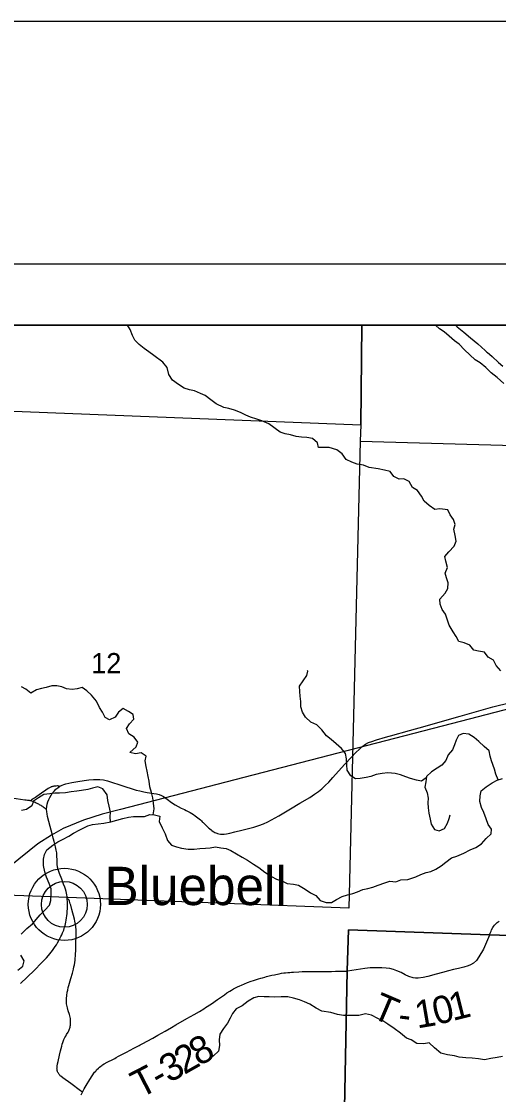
# Model space of a CAD drawing. Extents: x 0 to 34, y 0 to 22.
# Drawn here: x 4.145 to 5.129, y 19.787 to 22 of the extents above; entities that cross this region are included whole.
import ezdxf

# ---------------------------------------------------------------- set-up
doc = ezdxf.new("R2010")
doc.units = 0
for name, color, linetype in [('GM_X_Corporation', 7, 'Continuous'), ('GM_X_County_Road', 7, 'Continuous'), ('GM_X_Minor_River', 7, 'Continuous'), ('GM_X_Rail_Line', 7, 'Continuous'), ('GM_X_Section_Text', 7, 'Continuous'), ('GM_X_State_Route', 7, 'Continuous'), ('GM_X_Township_Road', 7, 'Continuous'), ('GM_X_Township_Road_Text', 7, 'Continuous'), ('GM_X_Unincorporated', 7, 'Continuous'), ('GM_X_Unincorporated_Location', 7, 'Continuous'), ('GM_X_Unincorporated_Text', 7, 'Continuous'), ('SH_Border', 7, 'Continuous'), ('SH_Cut_Line', 7, 'Continuous'), ('SH_Text', 7, 'Continuous')]:
    doc.layers.add(name, color=color, linetype=linetype)

msp = doc.modelspace()

# ---------------------------------------------------------------- linework, layer by layer
at = {"layer": 'GM_X_Corporation'}
for points in [[(4.7823, 18.128), (4.7905, 18.3604), (4.8074, 19.5455), (4.8169, 20.042), (4.8194, 20.1261), (5.11, 20.116), (6.0551, 20.0845), (6.4901, 20.0752), (6.7204, 20.0659), (7.3691, 20.0515), (7.3901, 20.051), (7.814, 20.0425), (8.4311, 20.028), (8.4311, 21.3734), (1.6311, 21.3734)], [(4.0508, 18.1454), (4.7823, 18.128), (4.7905, 18.3604), (4.8074, 19.5455), (4.8169, 20.042), (4.8194, 20.1261), (5.11, 20.116), (6.0551, 20.0845), (6.4901, 20.0752), (6.7204, 20.0659), (7.3691, 20.0515), (7.3901, 20.051), (7.814, 20.0425), (8.4311, 20.028), (8.4311, 21.3734), (2.7987, 21.3734)], [(8.4311, 14.5734), (8.4311, 20.028), (7.814, 20.0425), (7.3901, 20.051), (7.3691, 20.0515), (6.7204, 20.0659), (6.4901, 20.0752), (6.0551, 20.0845), (5.11, 20.116), (4.8194, 20.1261), (4.8169, 20.042), (4.8074, 19.5455), (4.7905, 18.3604), (4.7823, 18.128)], [(8.4311, 16.0029), (8.4311, 20.028), (7.814, 20.0425), (7.3901, 20.051), (7.3691, 20.0515), (6.7204, 20.0659), (6.4901, 20.0752), (6.0551, 20.0845), (5.11, 20.116), (4.8194, 20.1261), (4.8169, 20.042), (4.8074, 19.5455), (4.7905, 18.3604), (4.7823, 18.128)]]:
    msp.add_lwpolyline(points, dxfattribs=at)
for points in [[(4.8467, 21.3734), (3.8174, 21.3734), (3.8139, 21.2086), (4.8451, 21.1681)], [(5.8536, 21.3734), (4.8467, 21.3734), (4.8451, 21.1681), (4.8435, 21.134), (5.8473, 21.1062)], [(4.8451, 21.1681), (4.8435, 21.134), (4.8202, 20.1712), (3.8046, 20.2092), (3.8139, 21.2086)]]:
    msp.add_lwpolyline(points, close=True, dxfattribs=at)
at = {"layer": 'GM_X_County_Road'}
for points in [[(4.1641, 20.3929), (4.1656, 20.3942), (4.1674, 20.3957), (4.1692, 20.3971), (4.1704, 20.3979), (4.1716, 20.3987), (4.1742, 20.4003), (4.1768, 20.4021), (4.1816, 20.4054), (4.1864, 20.4089), (4.195, 20.415), (4.2002, 20.4182), (4.2024, 20.4195), (4.2036, 20.4201), (4.2047, 20.4207), (4.206, 20.4212), (4.2073, 20.4217), (4.2086, 20.4221), (4.2099, 20.4225), (4.2113, 20.4229), (4.2127, 20.4232), (4.2164, 20.4236), (4.2193, 20.4237), (4.2206, 20.4236), (4.2218, 20.4234), (4.2233, 20.4229), (4.2245, 20.4225)], [(4.0638, 20.4055), (4.0653, 20.4059), (4.0669, 20.4061), (4.0682, 20.4063), (4.0697, 20.4064), (4.0712, 20.4064), (4.0728, 20.4063), (4.0742, 20.4061), (4.0757, 20.406), (4.079, 20.4055), (4.087, 20.4043), (4.1164, 20.3997), (4.1518, 20.3948), (4.1546, 20.3945), (4.1575, 20.3941), (4.1592, 20.3939), (4.1608, 20.3936), (4.1624, 20.3933), (4.1641, 20.3929)], [(4.1641, 20.3929), (4.1659, 20.3923), (4.1677, 20.3917), (4.1696, 20.3909), (4.1714, 20.3902), (4.1732, 20.3894), (4.1751, 20.3885), (4.1767, 20.3877), (4.1784, 20.3869), (4.1801, 20.386), (4.1817, 20.3851), (4.1832, 20.3842), (4.1848, 20.3833), (4.1864, 20.3823), (4.1882, 20.3812), (4.1897, 20.3801), (4.1941, 20.3772), (4.197, 20.3753)]]:
    msp.add_lwpolyline(points, dxfattribs=at)
at = {"layer": 'GM_X_Minor_River'}
for points in [[(4.4178, 21.3111), (4.4079, 21.3185), (4.3984, 21.3253), (4.3881, 21.3335), (4.3786, 21.3425), (4.3743, 21.3523), (4.3689, 21.3644), (4.3639, 21.3734)], [(5.0169, 21.3599), (5.0074, 21.3658), (4.999, 21.3734)], [(5.1399, 21.2535), (5.1258, 21.2659), (5.114, 21.2752), (5.1026, 21.2861), (5.0908, 21.2962), (5.0805, 21.3022), (5.0695, 21.3123), (5.0588, 21.3228), (5.0477, 21.3344), (5.0378, 21.3415), (5.0272, 21.3509), (5.0169, 21.3599)], [(5.1334, 20.6605), (5.1242, 20.6714), (5.1185, 20.6823), (5.1078, 20.689), (5.0998, 20.6988), (5.0877, 20.7009), (5.0778, 20.7031), (5.0694, 20.7132), (5.058, 20.718), (5.0467, 20.7213), (5.0417, 20.7311), (5.0355, 20.7409), (5.0271, 20.7545), (5.0236, 20.7654), (5.0197, 20.7771), (5.0128, 20.7869), (5.0086, 20.7978), (5.0077, 20.8081), (5.0186, 20.8207), (5.0242, 20.8306), (5.0252, 20.842), (5.0213, 20.8522), (5.0186, 20.862), (5.0234, 20.8734), (5.0199, 20.8866), (5.0179, 20.8964), (5.0262, 20.906), (5.0374, 20.9179), (5.0415, 20.9278), (5.0398, 20.9399), (5.0367, 20.9527), (5.0393, 20.9622), (5.0362, 20.9724), (5.0289, 20.9822), (5.0246, 20.9924), (5.008, 20.9945), (4.9978, 20.9936), (4.9856, 21.0018), (4.9753, 21.0104), (4.97, 21.021), (4.9615, 21.0326), (4.9517, 21.039), (4.9447, 21.051), (4.9337, 21.0566), (4.9239, 21.0557), (4.9133, 21.0617), (4.9056, 21.0718), (4.8935, 21.0744), (4.8806, 21.0769), (4.8621, 21.0801), (4.8503, 21.0849), (4.8375, 21.0866), (4.8265, 21.0911), (4.8147, 21.0963), (4.8067, 21.1079), (4.7952, 21.1161), (4.7793, 21.1209), (4.7691, 21.1212), (4.7574, 21.121), (4.7558, 21.1309), (4.7451, 21.1398), (4.7338, 21.1416), (4.7224, 21.1426), (4.7118, 21.1437), (4.6997, 21.1473), (4.6887, 21.1491), (4.6789, 21.1528), (4.6553, 21.17), (4.6409, 21.1759), (4.6303, 21.1799), (4.6174, 21.1836), (4.6079, 21.1877), (4.5969, 21.1932), (4.5844, 21.198), (4.5726, 21.2017), (4.5624, 21.2038), (4.5464, 21.2116), (4.5354, 21.2195), (4.5236, 21.2288), (4.5141, 21.2329), (4.5016, 21.2384), (4.4918, 21.2399), (4.4808, 21.2435), (4.4686, 21.251), (4.4564, 21.2603), (4.4491, 21.2716), (4.4452, 21.286), (4.4368, 21.2969), (4.4178, 21.3111)], [(4.98, 20.4399), (4.9702, 20.4333), (4.9596, 20.4347), (4.9475, 20.4384), (4.938, 20.4421), (4.9266, 20.4461), (4.916, 20.4487), (4.9009, 20.4504), (4.8888, 20.4491), (4.8767, 20.4464), (4.8658, 20.4428), (4.8556, 20.4404), (4.8439, 20.4388), (4.8341, 20.4379), (4.8246, 20.4443), (4.8169, 20.4556), (4.816, 20.4669), (4.8156, 20.479), (4.8132, 20.49), (4.8052, 20.5002), (4.7941, 20.5103), (4.7835, 20.5189), (4.7739, 20.5267), (4.7644, 20.5391), (4.7541, 20.5489), (4.7419, 20.5548), (4.7305, 20.5649), (4.7247, 20.5755), (4.7213, 20.586), (4.7212, 20.597), (4.7199, 20.6084), (4.7191, 20.6182), (4.7182, 20.6288), (4.7261, 20.6399), (4.7335, 20.6506), (4.7354, 20.6601), (4.735, 20.6612)], [(4.4169, 20.3638), (4.4184, 20.3756), (4.4172, 20.3877), (4.4159, 20.3987), (4.4132, 20.4096), (4.4101, 20.4213), (4.4085, 20.4327), (4.4065, 20.4425), (4.4041, 20.4535), (4.4025, 20.4633), (4.4005, 20.4747), (4.4023, 20.4845), (4.3921, 20.4916), (4.38, 20.4896), (4.3686, 20.4918), (4.3818, 20.5036), (4.3851, 20.5132), (4.3774, 20.5237), (4.3668, 20.5308), (4.3618, 20.5413), (4.3677, 20.5509), (4.3767, 20.5608), (4.3755, 20.5706), (4.366, 20.5766), (4.355, 20.5829), (4.3452, 20.5752), (4.3385, 20.5653), (4.3268, 20.5595), (4.3174, 20.564), (4.312, 20.5753), (4.3058, 20.5851), (4.2997, 20.5979), (4.2894, 20.6103), (4.2798, 20.6196), (4.2703, 20.626), (4.2601, 20.6236), (4.2496, 20.622), (4.2382, 20.6234), (4.2283, 20.6274), (4.2177, 20.6296), (4.2079, 20.6299), (4.1962, 20.626), (4.1864, 20.624), (4.1762, 20.6212), (4.1642, 20.6143), (4.1543, 20.6225), (4.1448, 20.6277)], [(5.1279, 20.4356), (5.1232, 20.4474), (5.1208, 20.458), (5.1142, 20.4746), (5.1115, 20.4848), (5.1099, 20.4958), (5.0992, 20.5044), (5.0885, 20.5145), (5.0786, 20.5227), (5.0676, 20.5298), (5.0563, 20.5312), (5.0465, 20.5273), (5.0416, 20.5178), (5.038, 20.5079), (5.0339, 20.4976), (5.0253, 20.4873), (5.0201, 20.4755), (5.0122, 20.466), (5.0021, 20.4598), (4.9904, 20.4525), (4.9803, 20.4425), (4.9789, 20.4315), (4.9771, 20.4209), (4.9814, 20.4088), (4.9841, 20.3979), (4.9834, 20.388), (4.9839, 20.3782), (4.9855, 20.3668), (4.9879, 20.3547), (4.9902, 20.3441), (4.9971, 20.3336), (5.0066, 20.3303), (5.0172, 20.3353), (5.0239, 20.346), (5.0272, 20.3559), (5.029, 20.3635)], [(4.8063, 20.1948), (4.8172, 20.1987), (4.8286, 20.2015), (4.8384, 20.205), (4.8489, 20.2096), (4.8591, 20.2116), (4.8697, 20.2144), (4.881, 20.2187), (4.8941, 20.223), (4.9047, 20.2269), (4.9168, 20.2255), (4.9277, 20.2294), (4.9417, 20.2299), (4.9583, 20.2358), (4.9685, 20.2405), (4.9798, 20.2447), (4.9896, 20.2464), (4.9994, 20.2514), (5.0103, 20.2583), (5.02, 20.266), (5.0317, 20.2745), (5.043, 20.2784), (5.0573, 20.2846), (5.0701, 20.2912), (5.0818, 20.2962), (5.0938, 20.3039), (5.1035, 20.3146), (5.1136, 20.3242), (5.1147, 20.3337), (5.1078, 20.3435), (5.1032, 20.3555), (5.0985, 20.3684), (5.0939, 20.3789), (5.0904, 20.391), (5.0907, 20.4028), (5.0932, 20.413), (5.1037, 20.4215), (5.1158, 20.4292), (5.1259, 20.435), (5.1368, 20.4385)], [(4.3287, 20.3488), (4.3278, 20.3591), (4.3289, 20.369), (4.3261, 20.3814), (4.3234, 20.3928), (4.3218, 20.4049), (4.3126, 20.4169), (4.3027, 20.421), (4.2914, 20.4186), (4.2816, 20.4155), (4.2688, 20.4134), (4.259, 20.4122), (4.2476, 20.4109), (4.2359, 20.4089), (4.2235, 20.408), (4.2136, 20.4079), (4.2038, 20.4071), (4.191, 20.4054), (4.1801, 20.3989), (4.1699, 20.3919), (4.1662, 20.382), (4.1557, 20.3747), (4.1448, 20.3723)], [(4.1447, 20.1177), (4.1563, 20.1289), (4.1676, 20.1384), (4.1833, 20.1575), (4.193, 20.1667), (4.2032, 20.1775), (4.2053, 20.187), (4.206, 20.1995), (4.2063, 20.2112), (4.2024, 20.2218), (4.197, 20.235), (4.1931, 20.2459), (4.1907, 20.2588), (4.1906, 20.272), (4.1928, 20.2815), (4.1976, 20.2914), (4.21, 20.3007), (4.2198, 20.3076), (4.23, 20.3126), (4.2428, 20.3192), (4.2525, 20.3257), (4.2657, 20.3327), (4.2819, 20.3408), (4.2917, 20.3436), (4.303, 20.3452), (4.3147, 20.3461), (4.3291, 20.3489), (4.3419, 20.3528), (4.3539, 20.356), (4.3656, 20.3587), (4.3762, 20.3604), (4.3876, 20.3601), (4.3989, 20.3602), (4.4098, 20.3645), (4.4197, 20.3635), (4.4303, 20.3609), (4.4288, 20.3496), (4.435, 20.3364), (4.4412, 20.3243), (4.4462, 20.3107), (4.4546, 20.301), (4.4648, 20.2977), (4.4754, 20.2951), (4.4891, 20.2926), (4.5012, 20.2927), (4.5129, 20.2944), (4.5246, 20.2949), (4.5344, 20.2954), (4.5454, 20.2974), (4.5563, 20.2952), (4.5673, 20.2938), (4.5768, 20.2897), (4.6003, 20.2764), (4.6114, 20.27), (4.6239, 20.2618), (4.6349, 20.2547), (4.6467, 20.245), (4.6604, 20.2364), (4.6711, 20.2309), (4.6832, 20.2268), (4.6927, 20.222), (4.7059, 20.2203), (4.7161, 20.2185), (4.7298, 20.2103), (4.7412, 20.2024), (4.7519, 20.1969), (4.7614, 20.1871), (4.7735, 20.1827), (4.7841, 20.1824), (4.7947, 20.1886), (4.8063, 20.1948)], [(4.1374, 20.043), (4.1476, 20.0515), (4.1505, 20.0625), (4.144, 20.0742)], [(4.8093, 19.9499), (4.7966, 19.9514), (4.7831, 19.9555), (4.7645, 19.9587), (4.7531, 19.965), (4.7395, 19.9728), (4.7288, 19.978), (4.7186, 19.9817), (4.7061, 19.9854), (4.6943, 19.9883), (4.6804, 19.9881), (4.6671, 19.9872), (4.6558, 19.9882), (4.6456, 19.9878), (4.6346, 19.9888), (4.624, 19.986), (4.6128, 19.9791), (4.6, 19.9695), (4.588, 19.9633), (4.5805, 19.9537), (4.5756, 19.9442), (4.5697, 19.9335), (4.5619, 19.9225), (4.554, 19.911), (4.5526, 19.8996), (4.5535, 19.8879), (4.5513, 19.8758), (4.5412, 19.8666), (4.5314, 19.8596), (4.5329, 19.8585)], [(5.1369, 19.8648), (5.1263, 19.8633), (5.113, 19.8607), (5.0998, 19.8584), (5.0873, 19.8603), (5.0748, 19.8619), (5.0616, 19.8623), (5.048, 19.8638), (5.0378, 19.8661), (5.0234, 19.8688), (5.0102, 19.8718), (4.997, 19.8832), (4.986, 19.8931), (4.9751, 19.8912), (4.9607, 19.8916), (4.949, 19.8992), (4.9392, 19.903), (4.9267, 19.9132), (4.9139, 19.9231), (4.9007, 19.9319), (4.8905, 19.9383), (4.8799, 19.9436), (4.867, 19.9505), (4.8546, 19.9528), (4.8406, 19.9497), (4.8285, 19.9494), (4.816, 19.9494), (4.8093, 19.9499)]]:
    msp.add_lwpolyline(points, dxfattribs=at)
at = {"layer": 'GM_X_Rail_Line'}
msp.add_lwpolyline([(6.5148, 20.9732), (5.9587, 20.7967), (5.8659, 20.7679), (5.0311, 20.5511), (4.5849, 20.4354), (4.3494, 20.3746), (4.3114, 20.365), (4.2729, 20.3524), (4.2311, 20.3354), (4.2068, 20.3213), (4.1788, 20.304), (4.0429, 20.1945)], dxfattribs=at)
at = {"layer": 'GM_X_State_Route'}
msp.add_lwpolyline([(4.1431, 20.0156), (4.1571, 20.0289), (4.1717, 20.0432), (4.1865, 20.0583), (4.193, 20.0649), (4.1967, 20.0688), (4.2005, 20.0732), (4.2035, 20.0768), (4.2064, 20.0804), (4.2092, 20.0839), (4.212, 20.0879), (4.2145, 20.0916), (4.2171, 20.0957), (4.2195, 20.0997), (4.2222, 20.1043), (4.2243, 20.1082), (4.2265, 20.1126), (4.2282, 20.1162), (4.2298, 20.1199), (4.2311, 20.123), (4.2321, 20.1258), (4.2331, 20.1289), (4.234, 20.1317), (4.2349, 20.135), (4.2357, 20.1384), (4.2365, 20.1421), (4.2373, 20.1464), (4.2379, 20.1508), (4.2385, 20.155), (4.239, 20.1601), (4.2394, 20.1649), (4.2397, 20.1698), (4.2399, 20.1749), (4.24, 20.1793), (4.2399, 20.1837), (4.2396, 20.1903), (4.2394, 20.1947), (4.2388, 20.1985), (4.2379, 20.2021), (4.2372, 20.2051), (4.2356, 20.2104), (4.2342, 20.2145), (4.2319, 20.2208), (4.2296, 20.2266), (4.228, 20.2306), (4.2232, 20.2427), (4.2212, 20.2486), (4.2196, 20.2553), (4.2188, 20.2615), (4.2185, 20.269), (4.2183, 20.2794), (4.2178, 20.2849), (4.2168, 20.2909), (4.2154, 20.2975), (4.2127, 20.3083), (4.2114, 20.3131), (4.2107, 20.3155), (4.2097, 20.3191), (4.2083, 20.3244), (4.2062, 20.3322), (4.2042, 20.3394), (4.2015, 20.3496), (4.1989, 20.3599), (4.1979, 20.3655), (4.1973, 20.3698), (4.197, 20.3753), (4.1974, 20.3806), (4.1983, 20.3856), (4.1996, 20.3904), (4.2014, 20.3952), (4.2033, 20.3992), (4.2061, 20.4041), (4.2094, 20.4087), (4.213, 20.4131), (4.2161, 20.4162), (4.22, 20.4195), (4.2245, 20.4225), (4.2287, 20.4247), (4.2322, 20.4262), (4.2364, 20.4276), (4.2425, 20.4289), (4.2492, 20.4302), (4.2615, 20.4324), (4.2744, 20.4345), (4.2843, 20.4357), (4.2936, 20.4364), (4.2999, 20.4366), (4.3068, 20.4364), (4.3143, 20.4355), (4.3222, 20.4337), (4.3306, 20.4312), (4.3478, 20.4257), (4.3601, 20.4215), (4.3713, 20.4178), (4.3814, 20.4146), (4.3891, 20.4127), (4.3976, 20.411), (4.4044, 20.4099), (4.4179, 20.4078), (4.4234, 20.4068), (4.4289, 20.4053), (4.4336, 20.4034), (4.438, 20.401), (4.4452, 20.3959), (4.4548, 20.389), (4.462, 20.3843), (4.4684, 20.3805), (4.4744, 20.3774), (4.4811, 20.3742), (4.485, 20.3724), (4.4873, 20.3713), (4.4928, 20.3684), (4.4998, 20.3642), (4.5034, 20.3617), (4.5089, 20.3576), (4.5141, 20.3532), (4.5163, 20.3511), (4.518, 20.3494), (4.5186, 20.3487), (4.5195, 20.3477), (4.5224, 20.3447), (4.5237, 20.3436), (4.5245, 20.3428), (4.5266, 20.3407), (4.5301, 20.3375), (4.531, 20.3367), (4.5328, 20.3351), (4.5337, 20.3344), (4.536, 20.3325), (4.5379, 20.3311), (4.5403, 20.3294), (4.5419, 20.3285), (4.5439, 20.3274), (4.5478, 20.3259), (4.5495, 20.3253), (4.5523, 20.3245), (4.5558, 20.3239), (4.5594, 20.3236), (4.563, 20.3237), (4.5678, 20.3243), (4.5751, 20.3258), (4.5853, 20.3283), (4.5992, 20.3317), (4.6052, 20.3332), (4.6076, 20.3338), (4.6244, 20.3383), (4.6345, 20.3414), (4.6443, 20.3451), (4.6528, 20.3488), (4.661, 20.353), (4.6756, 20.3613), (4.6996, 20.3756), (4.7193, 20.3874), (4.7396, 20.3995), (4.7495, 20.4059), (4.7575, 20.4117), (4.7647, 20.4175), (4.7716, 20.4237), (4.7786, 20.4307), (4.7874, 20.4403), (4.8113, 20.4672), (4.8261, 20.4832), (4.8339, 20.4912), (4.8429, 20.4999), (4.8491, 20.5052), (4.8548, 20.5091), (4.861, 20.5124), (4.8679, 20.5151), (4.8774, 20.5182), (4.896, 20.5234), (4.9032, 20.5255), (4.9061, 20.5264), (4.9456, 20.5375), (4.9779, 20.5466), (5.0036, 20.554), (5.0495, 20.5673), (5.1172, 20.5861), (5.1539, 20.5955)], dxfattribs=at)
at = {"layer": 'GM_X_Township_Road'}
msp.add_line((4.2683, 19.7861), (4.2706, 19.7915), dxfattribs=at)
for points in [[(5.0401, 21.3734), (5.0439, 21.3703), (5.0572, 21.3591), (5.0711, 21.3477), (5.0863, 21.3348), (5.1011, 21.3216), (5.1044, 21.3187), (5.1063, 21.3171), (5.1101, 21.314), (5.1161, 21.3086), (5.1288, 21.2967), (5.1376, 21.2889)], [(4.2706, 19.7915), (4.2668, 19.7945), (4.2471, 19.8096), (4.2307, 19.8213), (4.2263, 19.8245), (4.2252, 19.8255), (4.2241, 19.8266), (4.223, 19.8277), (4.222, 19.829), (4.2211, 19.8304), (4.2203, 19.8318), (4.2197, 19.8333), (4.2192, 19.8345), (4.2189, 19.8358), (4.2185, 19.8373), (4.2184, 19.839), (4.2183, 19.8402), (4.2184, 19.8415), (4.2185, 19.8434), (4.2188, 19.8454), (4.2197, 19.8499), (4.2207, 19.8546), (4.2238, 19.8679), (4.2257, 19.877), (4.2281, 19.8866), (4.2292, 19.8902), (4.2303, 19.8938), (4.2312, 19.8962), (4.2319, 19.8983), (4.2327, 19.9001), (4.2334, 19.9015), (4.234, 19.9029), (4.2348, 19.9042), (4.2363, 19.9071), (4.2382, 19.9102), (4.2413, 19.9155), (4.2425, 19.9178), (4.2434, 19.9198), (4.2442, 19.9218), (4.2449, 19.9238), (4.2453, 19.9255), (4.2457, 19.9273), (4.2461, 19.9295), (4.2463, 19.9315), (4.2464, 19.9336), (4.2465, 19.9358), (4.2464, 19.9382), (4.2462, 19.9406), (4.2459, 19.9433), (4.2454, 19.946), (4.2448, 19.9489), (4.244, 19.9519), (4.2417, 19.9594), (4.2399, 19.9657), (4.2387, 19.9708), (4.2382, 19.9734), (4.2379, 19.9758), (4.2378, 19.9783), (4.2378, 19.9807), (4.2378, 19.9835), (4.238, 19.9863), (4.2383, 19.9897), (4.2388, 19.9931), (4.2392, 19.9955), (4.2396, 19.998), (4.2405, 20.0022), (4.2416, 20.0071), (4.2428, 20.0118), (4.2469, 20.026), (4.2503, 20.0372), (4.2523, 20.0449), (4.2533, 20.0497), (4.2542, 20.0544), (4.2549, 20.0588), (4.2556, 20.0635), (4.2561, 20.0678), (4.2564, 20.0721), (4.2567, 20.0773), (4.2569, 20.0824), (4.2571, 20.0901), (4.2573, 20.0978), (4.2579, 20.1144), (4.258, 20.1177), (4.258, 20.121), (4.2579, 20.1242), (4.2577, 20.1278), (4.2575, 20.131), (4.2572, 20.1339), (4.2567, 20.1373), (4.2561, 20.1407), (4.2553, 20.1445), (4.2543, 20.1482), (4.2487, 20.1683), (4.2466, 20.1773), (4.2458, 20.1801), (4.2451, 20.1827), (4.2441, 20.1857), (4.2433, 20.1874), (4.2426, 20.1885), (4.2412, 20.1895), (4.2396, 20.1903)], [(5.1102, 20.1155), (5.1119, 20.1197), (5.1135, 20.1237), (5.1147, 20.1265), (5.1169, 20.1308), (5.1184, 20.1334), (5.1207, 20.1362), (5.1232, 20.1388), (5.1264, 20.1416), (5.1304, 20.1444)], [(5.1102, 20.1155), (5.0977, 20.0866), (5.0885, 20.0704), (5.0836, 20.0633), (5.0773, 20.0575), (5.071, 20.054), (5.0664, 20.0521), (5.0574, 20.0496), (5.0462, 20.0467), (5.0358, 20.0443), (5.0254, 20.0417), (5.0132, 20.0384), (5.0003, 20.0349), (4.9834, 20.0301), (4.9733, 20.0281), (4.9633, 20.0268), (4.958, 20.0267), (4.9528, 20.0273), (4.944, 20.0299), (4.9366, 20.0334), (4.9281, 20.0381), (4.9193, 20.0419), (4.9124, 20.0444), (4.9049, 20.0463), (4.8973, 20.0473), (4.8884, 20.0479), (4.8733, 20.0479), (4.8639, 20.0476), (4.8533, 20.0466), (4.8171, 20.0414)], [(4.2706, 19.7915), (4.2744, 19.7982), (4.2784, 19.8053), (4.2859, 19.8174), (4.2908, 19.8254), (4.2921, 19.8275), (4.2946, 19.8308), (4.296, 19.8326), (4.2981, 19.835), (4.3, 19.8372), (4.3039, 19.8412), (4.3063, 19.8433), (4.3085, 19.8451), (4.3105, 19.8465), (4.312, 19.8477), (4.3155, 19.8499), (4.3215, 19.8531), (4.3346, 19.8598), (4.3374, 19.8612), (4.3406, 19.8629), (4.3454, 19.8654), (4.3617, 19.8741), (4.3765, 19.882), (4.3875, 19.8876), (4.3897, 19.8888), (4.3941, 19.891), (4.4158, 19.9031), (4.4266, 19.9092), (4.4411, 19.9174), (4.4545, 19.9252), (4.4637, 19.9304), (4.4864, 19.9437), (4.5009, 19.9517), (4.5121, 19.9582), (4.5211, 19.9636), (4.5248, 19.9659), (4.5368, 19.9737), (4.5495, 19.9825), (4.5637, 19.9925), (4.5689, 19.9961), (4.5751, 19.9999), (4.5785, 20.0021), (4.5825, 20.0044), (4.5868, 20.0067), (4.5907, 20.0086), (4.5954, 20.0109), (4.5991, 20.0125), (4.6047, 20.0148), (4.6112, 20.0174), (4.6185, 20.0201), (4.6234, 20.0217), (4.6297, 20.0238), (4.6341, 20.0251), (4.6385, 20.0265), (4.6424, 20.0276), (4.6467, 20.0288), (4.6507, 20.0298), (4.6561, 20.0313), (4.6615, 20.0326), (4.6669, 20.0338), (4.6693, 20.0344), (4.6729, 20.0351), (4.6766, 20.0358), (4.6815, 20.0366), (4.6859, 20.0373), (4.6894, 20.0377), (4.6941, 20.0382), (4.6986, 20.0386), (4.7017, 20.0388), (4.706, 20.0392), (4.7171, 20.04), (4.7239, 20.0403), (4.7394, 20.0405), (4.7587, 20.0405), (4.7692, 20.0405), (4.7767, 20.0406), (4.7841, 20.0407), (4.7926, 20.041), (4.7961, 20.0411), (4.7997, 20.041), (4.806, 20.041), (4.8171, 20.0414)]]:
    msp.add_lwpolyline(points, dxfattribs=at)
at = {"layer": 'GM_X_Unincorporated'}
for radius in [0.0744, 0.0472]:
    msp.add_circle((4.2336, 20.1788), radius, dxfattribs=at)
at = {"layer": 'GM_X_Unincorporated_Location'}
msp.add_line((4.2336, 20.1788), (4.2336, 20.1788), dxfattribs=at)
at = {"layer": 'SH_Border'}
msp.add_lwpolyline([(1.5, 21.5), (33.5, 21.5), (33.5, 0.5), (1.5, 0.5)], close=True, dxfattribs=at)
at = {"layer": 'SH_Cut_Line'}
msp.add_lwpolyline([(0, 0), (34, 0), (34, 22), (0, 22)], close=True, dxfattribs=at)
at = {"layer": 'SH_Text'}
msp.add_line((1.6311, 21.3734), (8.4311, 21.373), dxfattribs=at)

# ---------------------------------------------------------------- texts
at = {"layer": 'GM_X_Section_Text'}
msp.add_text('12', height=0.04186, rotation=0, dxfattribs=at).set_placement((4.2887, 20.6554))
at = {"layer": 'GM_X_Township_Road_Text'}
for s, rotation, p in [('T', 336.8695, (4.8643, 19.9463)), ('0', 14.1375, (5.0005, 19.9295)), ('1', 14.1395, (5.0344, 19.9381)), ('1', 9.6725, (4.9612, 19.9227)), ('-', 352.9181, (4.92, 19.9251)), ('8', 29.6297, (4.5112, 19.8441)), ('2', 29.5085, (4.4807, 19.8268)), ('3', 29.053, (4.4496, 19.8096)), ('T', 27.2896, (4.3897, 19.778)), ('-', 28.5689, (4.4287, 19.7982))]:
    msp.add_text(s, height=0.0568, rotation=rotation, dxfattribs=at).set_placement(p)
at = {"layer": 'GM_X_Unincorporated_Text'}
msp.add_text('Bluebell', height=0.07898, rotation=0, dxfattribs=at).set_placement((4.3164, 20.1774))

doc.saveas('drawing.dxf')
